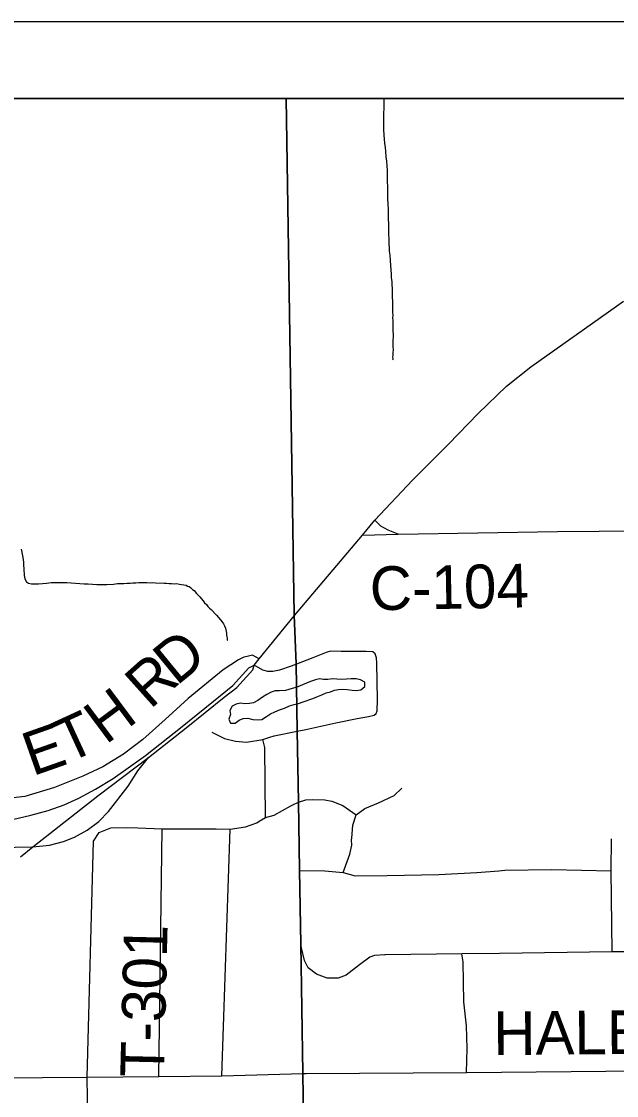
# Model space of a CAD drawing. Extents: x -59 to 82, y -3 to 49.
# Drawn here: x -50.961 to -50.187, y 47.994 to 49.391 of the extents above; entities that cross this region are included whole.
import ezdxf

# ---------------------------------------------------------------- set-up
doc = ezdxf.new("R2010")
doc.units = 0
for name, color, linetype in [('GM_X_Corporation', 7, 'Continuous'), ('GM_X_County_Road', 7, 'Continuous'), ('GM_X_County_Road_Text', 7, 'Continuous'), ('GM_X_Minor_Lake', 7, 'Continuous'), ('GM_X_Minor_River', 7, 'Continuous'), ('GM_X_State_Route', 7, 'Continuous'), ('GM_X_Township_Road', 7, 'Continuous'), ('GM_X_Township_Road_Text', 7, 'Continuous'), ('GM_X_US_Route', 7, 'Continuous'), ('SH_Data', 7, 'Continuous')]:
    doc.layers.add(name, color=color, linetype=linetype)

msp = doc.modelspace()

# ---------------------------------------------------------------- linework, layer by layer
at = {"layer": 'GM_X_Corporation'}
for p, q in [((-48.098, 49.2912), (-52.2242, 49.2912)), ((-50.6164, 49.2912), (-52.2242, 49.2912)), ((-50.6059, 48.6188), (-50.6164, 49.2912)), ((-48.098, 49.2912), (-50.6164, 49.2912)), ((-50.6164, 49.2912), (-50.6059, 48.6188)), ((-50.6032, 48.5554), (-50.6059, 48.6188)), ((-50.6059, 48.6188), (-50.6032, 48.5554)), ((-50.6021, 48.4683), (-50.6032, 48.5554)), ((-50.6032, 48.5554), (-50.6021, 48.4683)), ((-50.6004, 48.3759), (-50.6021, 48.4683)), ((-50.6021, 48.4683), (-50.6004, 48.3759)), ((-50.599, 48.287), (-50.6004, 48.3759)), ((-50.6004, 48.3759), (-50.599, 48.287)), ((-50.5974, 48.1913), (-50.599, 48.287)), ((-50.599, 48.287), (-50.5974, 48.1913)), ((-50.5946, 48.023), (-50.5974, 48.1913)), ((-50.5974, 48.1913), (-50.5946, 48.023)), ((-50.5865, 47.5304), (-50.5946, 48.023)), ((-50.5946, 48.023), (-50.5865, 47.5304))]:
    msp.add_line(p, q, dxfattribs=at)
at = {"layer": 'GM_X_County_Road'}
for p, q in [((-50.4934, 48.7345), (-50.5009, 48.7425)), ((-50.4837, 48.7292), (-50.4934, 48.7345)), ((-50.5171, 48.7229), (-50.4706, 48.7241)), ((-50.4706, 48.7241), (-50.4837, 48.7292)), ((-50.4706, 48.7241), (-50.2635, 48.7277)), ((-50.2635, 48.7277), (-50.0858, 48.7292)), ((-50.6715, 48.5643), (-50.6784, 48.5608)), ((-50.6671, 48.5651), (-50.6715, 48.5643)), ((-50.6602, 48.5665), (-50.6671, 48.5651)), ((-50.6515, 48.562), (-50.6602, 48.5665)), ((-50.6784, 48.5608), (-50.6983, 48.5475)), ((-50.6983, 48.5475), (-50.7438, 48.5104)), ((-50.7438, 48.5104), (-50.7736, 48.4828)), ((-50.7736, 48.4828), (-50.8026, 48.4571)), ((-50.8026, 48.4571), (-50.8279, 48.4377)), ((-50.8279, 48.4377), (-50.8547, 48.4212)), ((-50.8547, 48.4212), (-50.8809, 48.4093)), ((-50.8809, 48.4093), (-50.9176, 48.3943)), ((-50.9564, 48.3826), (-50.9822, 48.3798)), ((-50.9176, 48.3943), (-50.9564, 48.3826)), ((-50.7819, 48.0186), (-50.6999, 48.0193)), ((-50.6999, 48.0193), (-50.5944, 48.0224)), ((-50.5944, 48.0224), (-50.5905, 48.0225)), ((-50.5905, 48.0225), (-50.3819, 48.0235)), ((-50.3819, 48.0235), (-50.0854, 48.0268)), ((-51.0128, 48.0167), (-50.8752, 48.0178)), ((-50.8752, 48.0178), (-50.7819, 48.0186)), ((-50.8669, 47.5839), (-50.8752, 48.0178))]:
    msp.add_line(p, q, dxfattribs=at)
at = {"layer": 'GM_X_Minor_Lake'}
for p, q in [((-50.5252, 48.5361), (-50.5317, 48.5357)), ((-50.5195, 48.5347), (-50.5252, 48.5361)), ((-50.6011, 48.5255), (-50.6171, 48.5207)), ((-50.5951, 48.5282), (-50.6011, 48.5255)), ((-50.5898, 48.5301), (-50.5951, 48.5282)), ((-50.5845, 48.5325), (-50.5898, 48.5301)), ((-50.5784, 48.5348), (-50.5845, 48.5325)), ((-50.5731, 48.536), (-50.5784, 48.5348)), ((-50.5678, 48.5349), (-50.5731, 48.536)), ((-50.5621, 48.535), (-50.5678, 48.5349)), ((-50.556, 48.5358), (-50.5621, 48.535)), ((-50.5503, 48.5355), (-50.556, 48.5358)), ((-50.5438, 48.5352), (-50.5503, 48.5355)), ((-50.5483, 48.5219), (-50.5429, 48.5223)), ((-50.5378, 48.5353), (-50.5438, 48.5352)), ((-50.5429, 48.5223), (-50.5369, 48.522)), ((-50.5317, 48.5357), (-50.5378, 48.5353)), ((-50.5142, 48.5317), (-50.5195, 48.5347)), ((-50.5194, 48.5218), (-50.5141, 48.526)), ((-50.5141, 48.526), (-50.5142, 48.5317)), ((-50.6473, 48.5121), (-50.6534, 48.5075)), ((-50.6413, 48.5156), (-50.6473, 48.5121)), ((-50.636, 48.5187), (-50.6413, 48.5156)), ((-50.6307, 48.5202), (-50.636, 48.5187)), ((-50.625, 48.5203), (-50.6307, 48.5202)), ((-50.6171, 48.5207), (-50.625, 48.5203)), ((-50.5941, 48.5058), (-50.5816, 48.5101)), ((-50.5816, 48.5101), (-50.5763, 48.5125)), ((-50.5763, 48.5125), (-50.5698, 48.5152)), ((-50.5698, 48.5152), (-50.5645, 48.5175)), ((-50.5645, 48.5175), (-50.5589, 48.5191)), ((-50.5589, 48.5191), (-50.5536, 48.521)), ((-50.5536, 48.521), (-50.5483, 48.5219)), ((-50.5369, 48.522), (-50.5304, 48.5213)), ((-50.5304, 48.5213), (-50.5251, 48.5206)), ((-50.5251, 48.5206), (-50.5194, 48.5218)), ((-50.6867, 48.5003), (-50.6897, 48.4949)), ((-50.6897, 48.4949), (-50.6889, 48.4893)), ((-50.6814, 48.503), (-50.6867, 48.5003)), ((-50.6757, 48.5042), (-50.6814, 48.503)), ((-50.67, 48.5035), (-50.6757, 48.5042)), ((-50.664, 48.5036), (-50.67, 48.5035)), ((-50.6587, 48.5048), (-50.664, 48.5036)), ((-50.6534, 48.5075), (-50.6587, 48.5048)), ((-50.6312, 48.4929), (-50.6251, 48.4956)), ((-50.6251, 48.4956), (-50.6187, 48.4976)), ((-50.6187, 48.4976), (-50.6122, 48.5007)), ((-50.6122, 48.5007), (-50.6058, 48.5023)), ((-50.6058, 48.5023), (-50.6005, 48.5039)), ((-50.6005, 48.5039), (-50.5941, 48.5058)), ((-50.6889, 48.4893), (-50.6911, 48.4835)), ((-50.6911, 48.4835), (-50.6888, 48.4782)), ((-50.6827, 48.4783), (-50.6774, 48.4822)), ((-50.6774, 48.4822), (-50.6721, 48.4841)), ((-50.6721, 48.4841), (-50.666, 48.4846)), ((-50.666, 48.4846), (-50.6599, 48.4831)), ((-50.6599, 48.4831), (-50.6539, 48.4824)), ((-50.6539, 48.4824), (-50.6482, 48.4832)), ((-50.6482, 48.4832), (-50.6421, 48.4867)), ((-50.6421, 48.4867), (-50.6368, 48.4902)), ((-50.6368, 48.4902), (-50.6312, 48.4929)), ((-50.6888, 48.4782), (-50.6827, 48.4783))]:
    msp.add_line(p, q, dxfattribs=at)
at = {"layer": 'GM_X_Minor_River'}
for p, q in [((-50.4892, 49.2912), (-50.4893, 49.2902)), ((-50.4894, 49.2776), (-50.4897, 49.2723)), ((-50.4892, 49.2853), (-50.4894, 49.2776)), ((-50.4893, 49.2902), (-50.4892, 49.2853)), ((-50.4896, 49.2674), (-50.4899, 49.262)), ((-50.4897, 49.2723), (-50.4896, 49.2674)), ((-50.4899, 49.262), (-50.4898, 49.2563)), ((-50.4898, 49.2563), (-50.4896, 49.2503)), ((-50.4896, 49.2503), (-50.4895, 49.2438)), ((-50.4895, 49.2438), (-50.489, 49.2381)), ((-50.489, 49.2381), (-50.4885, 49.2328)), ((-50.4885, 49.2328), (-50.4876, 49.2271)), ((-50.4876, 49.2271), (-50.4871, 49.2222)), ((-50.4871, 49.2222), (-50.4866, 49.215)), ((-50.4866, 49.215), (-50.4857, 49.2093)), ((-50.4857, 49.2093), (-50.4856, 49.2032)), ((-50.4856, 49.2032), (-50.4851, 49.1975)), ((-50.4851, 49.1975), (-50.485, 49.1918)), ((-50.485, 49.1918), (-50.4849, 49.1869)), ((-50.4849, 49.1869), (-50.4848, 49.1823)), ((-50.4848, 49.1823), (-50.4847, 49.177)), ((-50.4847, 49.177), (-50.4846, 49.1717)), ((-50.4846, 49.1717), (-50.4845, 49.166)), ((-50.4845, 49.166), (-50.4844, 49.1599)), ((-50.4844, 49.1599), (-50.4839, 49.1542)), ((-50.4839, 49.1542), (-50.4837, 49.1466)), ((-50.4837, 49.1466), (-50.4836, 49.1405)), ((-50.4836, 49.1405), (-50.4835, 49.1344)), ((-50.4835, 49.1344), (-50.4833, 49.128)), ((-50.4833, 49.128), (-50.4832, 49.1215)), ((-50.4832, 49.1215), (-50.4828, 49.1017)), ((-50.4828, 49.1017), (-50.4823, 49.0968)), ((-50.4823, 49.0968), (-50.4822, 49.0922)), ((-50.4822, 49.0922), (-50.4817, 49.0873)), ((-50.4817, 49.0873), (-50.4812, 49.0801)), ((-50.4812, 49.0801), (-50.4807, 49.0736)), ((-50.4807, 49.0736), (-50.4802, 49.068)), ((-50.4802, 49.068), (-50.4797, 49.0623)), ((-50.4797, 49.0623), (-50.4796, 49.0577)), ((-50.4796, 49.0577), (-50.4791, 49.0531)), ((-50.4791, 49.0531), (-50.479, 49.0486)), ((-50.479, 49.0486), (-50.4786, 49.0437)), ((-50.4786, 49.0437), (-50.4784, 49.0383)), ((-50.4784, 49.0383), (-50.4783, 49.0323)), ((-50.4783, 49.0323), (-50.4782, 49.0273)), ((-50.4782, 49.0273), (-50.4781, 49.0231)), ((-50.4781, 49.0231), (-50.478, 49.017)), ((-50.478, 49.017), (-50.4779, 49.0125)), ((-50.4779, 49.0125), (-50.4778, 49.0091)), ((-50.4778, 49.0091), (-50.4782, 49.0056)), ((-50.4782, 49.0056), (-50.4777, 49.0022)), ((-50.4777, 49.0022), (-50.4776, 48.9988)), ((-50.4776, 48.9988), (-50.4776, 48.9946)), ((-50.4776, 48.9946), (-50.4775, 48.9908)), ((-50.4775, 48.9908), (-50.4774, 48.9878)), ((-50.4774, 48.9878), (-50.4773, 48.9847)), ((-50.4773, 48.9847), (-50.4773, 48.9809)), ((-50.4773, 48.9809), (-50.4776, 48.9764)), ((-50.4776, 48.9764), (-50.4775, 48.973)), ((-50.4775, 48.973), (-50.4774, 48.9684)), ((-50.4775, 48.9566), (-50.4779, 48.9547)), ((-50.4773, 48.9642), (-50.4776, 48.9604)), ((-50.4776, 48.9604), (-50.4775, 48.9566)), ((-50.4774, 48.9684), (-50.4773, 48.9642)), ((-50.4778, 48.9513), (-50.4782, 48.9505)), ((-50.4779, 48.9547), (-50.4778, 48.9524)), ((-50.4778, 48.9524), (-50.4778, 48.9513)), ((-50.9609, 48.7048), (-50.9605, 48.7029)), ((-50.9605, 48.7029), (-50.9584, 48.6911)), ((-50.9584, 48.6911), (-50.9579, 48.6873)), ((-50.9579, 48.6873), (-50.9578, 48.6835)), ((-50.9578, 48.6835), (-50.9577, 48.6794)), ((-50.9577, 48.6794), (-50.9577, 48.6759)), ((-50.9577, 48.6759), (-50.9572, 48.6733)), ((-50.9572, 48.6733), (-50.9572, 48.6702)), ((-50.9572, 48.6702), (-50.9567, 48.6683)), ((-50.9567, 48.6683), (-50.9559, 48.6653)), ((-50.9559, 48.6653), (-50.9543, 48.6623)), ((-50.9543, 48.6623), (-50.9516, 48.6605)), ((-50.9516, 48.6605), (-50.9478, 48.6594)), ((-50.9478, 48.6594), (-50.9455, 48.6594)), ((-50.9455, 48.6594), (-50.9421, 48.6595)), ((-50.9421, 48.6595), (-50.9383, 48.6596)), ((-50.9383, 48.6596), (-50.9333, 48.6601)), ((-50.9333, 48.6601), (-50.928, 48.6606)), ((-50.928, 48.6606), (-50.9219, 48.6611)), ((-50.9219, 48.6611), (-50.9158, 48.6612)), ((-50.9158, 48.6612), (-50.9074, 48.6614)), ((-50.9074, 48.6614), (-50.9017, 48.6611)), ((-50.9017, 48.6611), (-50.896, 48.6608)), ((-50.896, 48.6608), (-50.8903, 48.6602)), ((-50.8903, 48.6602), (-50.8849, 48.6599)), ((-50.8849, 48.6599), (-50.8792, 48.6596)), ((-50.8792, 48.6596), (-50.8739, 48.6594)), ((-50.8739, 48.6594), (-50.8681, 48.6591)), ((-50.8681, 48.6591), (-50.8624, 48.6588)), ((-50.8624, 48.6588), (-50.8563, 48.6586)), ((-50.8563, 48.6586), (-50.8498, 48.6587)), ((-50.8498, 48.6587), (-50.8411, 48.6593)), ((-50.8411, 48.6593), (-50.8358, 48.6598)), ((-50.8358, 48.6598), (-50.8312, 48.6598)), ((-50.8312, 48.6598), (-50.8274, 48.6599)), ((-50.8274, 48.6599), (-50.8232, 48.6604)), ((-50.8232, 48.6604), (-50.8194, 48.6605)), ((-50.8194, 48.6605), (-50.816, 48.6609)), ((-50.816, 48.6609), (-50.8118, 48.661)), ((-50.8118, 48.661), (-50.808, 48.6611)), ((-50.808, 48.6611), (-50.8046, 48.6611)), ((-50.8046, 48.6611), (-50.8011, 48.6612)), ((-50.8011, 48.6612), (-50.7977, 48.6613)), ((-50.7977, 48.6613), (-50.7931, 48.661)), ((-50.7931, 48.661), (-50.7897, 48.6611)), ((-50.7897, 48.6611), (-50.7863, 48.6607)), ((-50.7863, 48.6607), (-50.7752, 48.6602)), ((-50.7752, 48.6602), (-50.7718, 48.6603)), ((-50.7718, 48.6603), (-50.7687, 48.66)), ((-50.7687, 48.66), (-50.7657, 48.66)), ((-50.7657, 48.66), (-50.7622, 48.6597)), ((-50.7622, 48.6597), (-50.7588, 48.6598)), ((-50.7588, 48.6598), (-50.755, 48.6591)), ((-50.755, 48.6591), (-50.7523, 48.6588)), ((-50.7523, 48.6588), (-50.7496, 48.6584)), ((-50.7496, 48.6584), (-50.7466, 48.6577)), ((-50.7466, 48.6577), (-50.7446, 48.6566)), ((-50.7446, 48.6566), (-50.7427, 48.6559)), ((-50.7427, 48.6559), (-50.7408, 48.6548)), ((-50.7408, 48.6548), (-50.7381, 48.6522)), ((-50.7381, 48.6522), (-50.7361, 48.6507)), ((-50.7361, 48.6507), (-50.733, 48.647)), ((-50.733, 48.647), (-50.7307, 48.6447)), ((-50.7307, 48.6447), (-50.7287, 48.6425)), ((-50.7287, 48.6425), (-50.7268, 48.6403)), ((-50.7268, 48.6403), (-50.7244, 48.6376)), ((-50.7244, 48.6376), (-50.7225, 48.635)), ((-50.7225, 48.635), (-50.7201, 48.6328)), ((-50.7201, 48.6328), (-50.7182, 48.6302)), ((-50.7182, 48.6302), (-50.7162, 48.6279)), ((-50.7162, 48.6279), (-50.7139, 48.6261)), ((-50.7139, 48.6261), (-50.712, 48.6242)), ((-50.712, 48.6242), (-50.7085, 48.6205)), ((-50.7085, 48.6205), (-50.7069, 48.6186)), ((-50.7069, 48.6186), (-50.7045, 48.6156)), ((-50.7045, 48.6156), (-50.7018, 48.6126)), ((-50.7018, 48.6126), (-50.7002, 48.6104)), ((-50.7002, 48.6104), (-50.6979, 48.6074)), ((-50.6979, 48.6074), (-50.6967, 48.6047)), ((-50.6967, 48.6047), (-50.6951, 48.6017)), ((-50.6951, 48.6017), (-50.6947, 48.5998)), ((-50.6947, 48.5998), (-50.6943, 48.5976)), ((-50.6943, 48.5976), (-50.6938, 48.5953)), ((-50.6938, 48.5953), (-50.6938, 48.5926)), ((-50.6938, 48.5926), (-50.6934, 48.5907)), ((-50.6934, 48.5907), (-50.6933, 48.5888)), ((-50.6933, 48.5888), (-50.6929, 48.5862)), ((-50.6929, 48.5862), (-50.6929, 48.5862)), ((-50.6929, 48.5862), (-50.6925, 48.5862))]:
    msp.add_line(p, q, dxfattribs=at)
at = {"layer": 'GM_X_State_Route'}
for p, q in [((-50.8412, 48.4061), (-50.7992, 48.436)), ((-50.8095, 48.416), (-50.7952, 48.4335)), ((-50.8219, 48.3964), (-50.8095, 48.416)), ((-50.8642, 48.3923), (-50.8412, 48.4061)), ((-50.8473, 48.3633), (-50.8219, 48.3964)), ((-50.8862, 48.3805), (-50.8642, 48.3923)), ((-50.9259, 48.3646), (-50.9053, 48.3718)), ((-50.9053, 48.3718), (-50.8862, 48.3805)), ((-50.9796, 48.3513), (-50.9483, 48.3583)), ((-50.9483, 48.3583), (-50.9259, 48.3646)), ((-50.8602, 48.3504), (-50.8473, 48.3633)), ((-50.8754, 48.339), (-50.8602, 48.3504)), ((-50.9059, 48.3241), (-50.8918, 48.33)), ((-50.8918, 48.33), (-50.8754, 48.339)), ((-51.0695, 48.3155), (-50.946, 48.3171)), ((-50.946, 48.3171), (-50.9243, 48.3195)), ((-50.9243, 48.3195), (-50.9059, 48.3241))]:
    msp.add_line(p, q, dxfattribs=at)
at = {"layer": 'GM_X_Township_Road'}
for p, q in [((-50.5642, 48.5702), (-50.5815, 48.5633)), ((-50.5586, 48.5718), (-50.5642, 48.5702)), ((-50.545, 48.5713), (-50.5586, 48.5718)), ((-50.5125, 48.5716), (-50.545, 48.5713)), ((-50.5037, 48.5711), (-50.5125, 48.5716)), ((-50.5008, 48.5684), (-50.5037, 48.5711)), ((-50.499, 48.5632), (-50.5008, 48.5684)), ((-50.6466, 48.547), (-50.6581, 48.5537)), ((-50.6097, 48.5525), (-50.6251, 48.5472)), ((-50.603, 48.5549), (-50.6097, 48.5525)), ((-50.5815, 48.5633), (-50.603, 48.5549)), ((-50.4983, 48.5564), (-50.499, 48.5632)), ((-50.4976, 48.5086), (-50.4983, 48.5564)), ((-50.64, 48.5456), (-50.6466, 48.547)), ((-50.6339, 48.5454), (-50.64, 48.5456)), ((-50.6251, 48.5472), (-50.6339, 48.5454)), ((-50.4978, 48.4944), (-50.4976, 48.5086)), ((-50.4994, 48.4908), (-50.4978, 48.4944)), ((-50.5516, 48.4786), (-50.524, 48.4844)), ((-50.524, 48.4844), (-50.5091, 48.4869)), ((-50.5091, 48.4869), (-50.5019, 48.4885)), ((-50.5019, 48.4885), (-50.4994, 48.4908)), ((-50.713, 48.4663), (-50.6965, 48.4582)), ((-50.6321, 48.4616), (-50.6019, 48.4677)), ((-50.6019, 48.4677), (-50.5909, 48.4701)), ((-50.5909, 48.4701), (-50.5516, 48.4786)), ((-50.6965, 48.4582), (-50.6822, 48.4546)), ((-50.6822, 48.4546), (-50.6679, 48.4536)), ((-50.6679, 48.4536), (-50.6466, 48.4571)), ((-50.6466, 48.4571), (-50.6375, 48.46)), ((-50.6439, 48.4464), (-50.6466, 48.4571)), ((-50.6375, 48.46), (-50.6321, 48.4616)), ((-50.6431, 48.3555), (-50.6439, 48.4464)), ((-50.4964, 48.3744), (-50.476, 48.384)), ((-50.476, 48.384), (-50.4659, 48.3935)), ((-50.6318, 48.3587), (-50.6103, 48.3706)), ((-50.6103, 48.3706), (-50.6075, 48.3719)), ((-50.6075, 48.3719), (-50.6002, 48.3753)), ((-50.6002, 48.3753), (-50.5909, 48.3783)), ((-50.5909, 48.3783), (-50.5824, 48.3789)), ((-50.5824, 48.3789), (-50.5662, 48.3783)), ((-50.5662, 48.3783), (-50.5568, 48.3766)), ((-50.5568, 48.3766), (-50.5427, 48.371)), ((-50.5427, 48.371), (-50.5255, 48.3591)), ((-50.5141, 48.367), (-50.4964, 48.3744)), ((-50.6513, 48.3505), (-50.6431, 48.3555)), ((-50.6431, 48.3555), (-50.6318, 48.3587)), ((-50.5297, 48.3456), (-50.5255, 48.3591)), ((-50.5255, 48.3591), (-50.5141, 48.367)), ((-50.8597, 48.336), (-50.8444, 48.3421)), ((-50.8444, 48.3421), (-50.8234, 48.3426)), ((-50.8234, 48.3426), (-50.8095, 48.342)), ((-50.8095, 48.342), (-50.7775, 48.3408)), ((-50.7819, 48.0186), (-50.7775, 48.3408)), ((-50.7775, 48.3408), (-50.7075, 48.3408)), ((-50.7075, 48.3408), (-50.6892, 48.3401)), ((-50.6892, 48.3401), (-50.6694, 48.3433)), ((-50.6694, 48.3433), (-50.6546, 48.3484)), ((-50.6546, 48.3484), (-50.6513, 48.3505)), ((-50.5311, 48.3285), (-50.5297, 48.3456)), ((-50.8671, 48.3246), (-50.8597, 48.336)), ((-50.6999, 48.0193), (-50.6892, 48.3401)), ((-50.5313, 48.3262), (-50.5311, 48.3285)), ((-50.1937, 48.2859), (-50.1934, 48.3277)), ((-50.8752, 48.0178), (-50.8671, 48.3246)), ((-50.5337, 48.3079), (-50.5311, 48.3193)), ((-50.5311, 48.3193), (-50.5313, 48.3262)), ((-50.5422, 48.2841), (-50.5337, 48.3079)), ((-50.5972, 48.1907), (-50.5988, 48.2865)), ((-50.5988, 48.2865), (-50.566, 48.286)), ((-50.566, 48.286), (-50.5422, 48.2841)), ((-50.3682, 48.2837), (-50.3396, 48.2862)), ((-50.3396, 48.2862), (-50.3319, 48.2868)), ((-50.3319, 48.2868), (-50.2706, 48.288)), ((-50.2706, 48.288), (-50.1937, 48.2859)), ((-50.1925, 48.1805), (-50.1937, 48.2859)), ((-50.5422, 48.2841), (-50.5266, 48.2796)), ((-50.5266, 48.2796), (-50.4848, 48.2802)), ((-50.4848, 48.2802), (-50.4179, 48.2812)), ((-50.4179, 48.2812), (-50.3682, 48.2837)), ((-50.5962, 48.1859), (-50.5972, 48.1907)), ((-50.5927, 48.1695), (-50.5962, 48.1859)), ((-50.5077, 48.1737), (-50.5211, 48.1636)), ((-50.5016, 48.1759), (-50.5077, 48.1737)), ((-50.4881, 48.1766), (-50.5016, 48.1759)), ((-50.4871, 48.1767), (-50.4881, 48.1766)), ((-50.3877, 48.178), (-50.4871, 48.1767)), ((-50.3389, 48.1787), (-50.3877, 48.178)), ((-50.3861, 48.1676), (-50.3877, 48.178)), ((-50.1925, 48.1805), (-50.3389, 48.1787)), ((-50.0801, 48.1812), (-50.1925, 48.1805)), ((-50.5876, 48.1599), (-50.5927, 48.1695)), ((-50.577, 48.1516), (-50.5876, 48.1599)), ((-50.5211, 48.1636), (-50.5383, 48.1504)), ((-50.3853, 48.1156), (-50.3861, 48.1676)), ((-50.5629, 48.1465), (-50.577, 48.1516)), ((-50.5485, 48.1464), (-50.5629, 48.1465)), ((-50.5383, 48.1504), (-50.5485, 48.1464)), ((-50.3816, 48.0846), (-50.3853, 48.1156)), ((-50.3809, 48.055), (-50.3816, 48.0846)), ((-50.3819, 48.0235), (-50.3809, 48.055))]:
    msp.add_line(p, q, dxfattribs=at)
at = {"layer": 'GM_X_US_Route'}
for p, q in [((-50.1867, 49.0208), (-50.1777, 49.0272)), ((-50.2982, 48.942), (-50.1867, 49.0208)), ((-50.3298, 48.9169), (-50.2982, 48.942)), ((-50.3666, 48.8812), (-50.3298, 48.9169)), ((-50.4054, 48.8414), (-50.3666, 48.8812)), ((-50.4522, 48.7942), (-50.4054, 48.8414)), ((-50.5009, 48.7425), (-50.4522, 48.7942)), ((-50.5171, 48.7229), (-50.5009, 48.7425)), ((-50.6057, 48.6182), (-50.5171, 48.7229)), ((-50.6515, 48.562), (-50.6057, 48.6182)), ((-50.6856, 48.5271), (-50.6647, 48.5502)), ((-50.6647, 48.5502), (-50.6581, 48.5537)), ((-50.6598, 48.5478), (-50.6581, 48.5537)), ((-50.6581, 48.5537), (-50.6515, 48.562)), ((-50.6807, 48.5247), (-50.6598, 48.5478)), ((-50.7017, 48.5143), (-50.6856, 48.5271)), ((-50.6968, 48.5119), (-50.6807, 48.5247)), ((-50.7515, 48.4737), (-50.7017, 48.5143)), ((-50.7464, 48.4723), (-50.6968, 48.5119)), ((-50.7992, 48.436), (-50.7515, 48.4737)), ((-50.7952, 48.4335), (-50.7464, 48.4723)), ((-50.8611, 48.3837), (-50.7952, 48.4335)), ((-50.946, 48.3171), (-50.8611, 48.3837)), ((-50.9617, 48.3045), (-50.946, 48.3171))]:
    msp.add_line(p, q, dxfattribs=at)
at = {"layer": 'SH_Data'}
for p, q in [((-54.998, 49.3912), (-47.998, 49.3912)), ((-54.898, 49.2912), (-48.098, 49.2912))]:
    msp.add_line(p, q, dxfattribs=at)

# ---------------------------------------------------------------- texts
at = {"layer": 'GM_X_County_Road_Text'}
for s, height, rotation, p in [('C-104', 0.05682, 1.1021, (-50.5071, 48.625)), ('D', 0.0568, 39.2799, (-50.759, 48.526)), ('R', 0.0568, 41.8578, (-50.7933, 48.4953)), ('H', 0.0568, 36.6682, (-50.8511, 48.4495)), ('T', 0.0568, 24.6426, (-50.901, 48.4252)), ('E', 0.0568, 19.4388, (-50.9463, 48.4089)), ('HALE', 0.05682, 0.5159, (-50.3467, 48.0462))]:
    msp.add_text(s, height=height, rotation=rotation, dxfattribs=at).set_placement(p)
at = {"layer": 'GM_X_Township_Road_Text'}
msp.add_text('T-301', height=0.05682, rotation=88.5957, dxfattribs=at).set_placement((-50.7754, 48.0171))

doc.saveas('drawing.dxf')
